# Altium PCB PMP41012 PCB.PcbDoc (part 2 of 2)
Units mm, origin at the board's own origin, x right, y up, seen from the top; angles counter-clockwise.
Board outline 69 x 32 mm, 2 copper layers (Top Layer, Bottom Layer), stack 1.575 mm thick; 63 components, 34 nets, 139 pads, 27 vias.
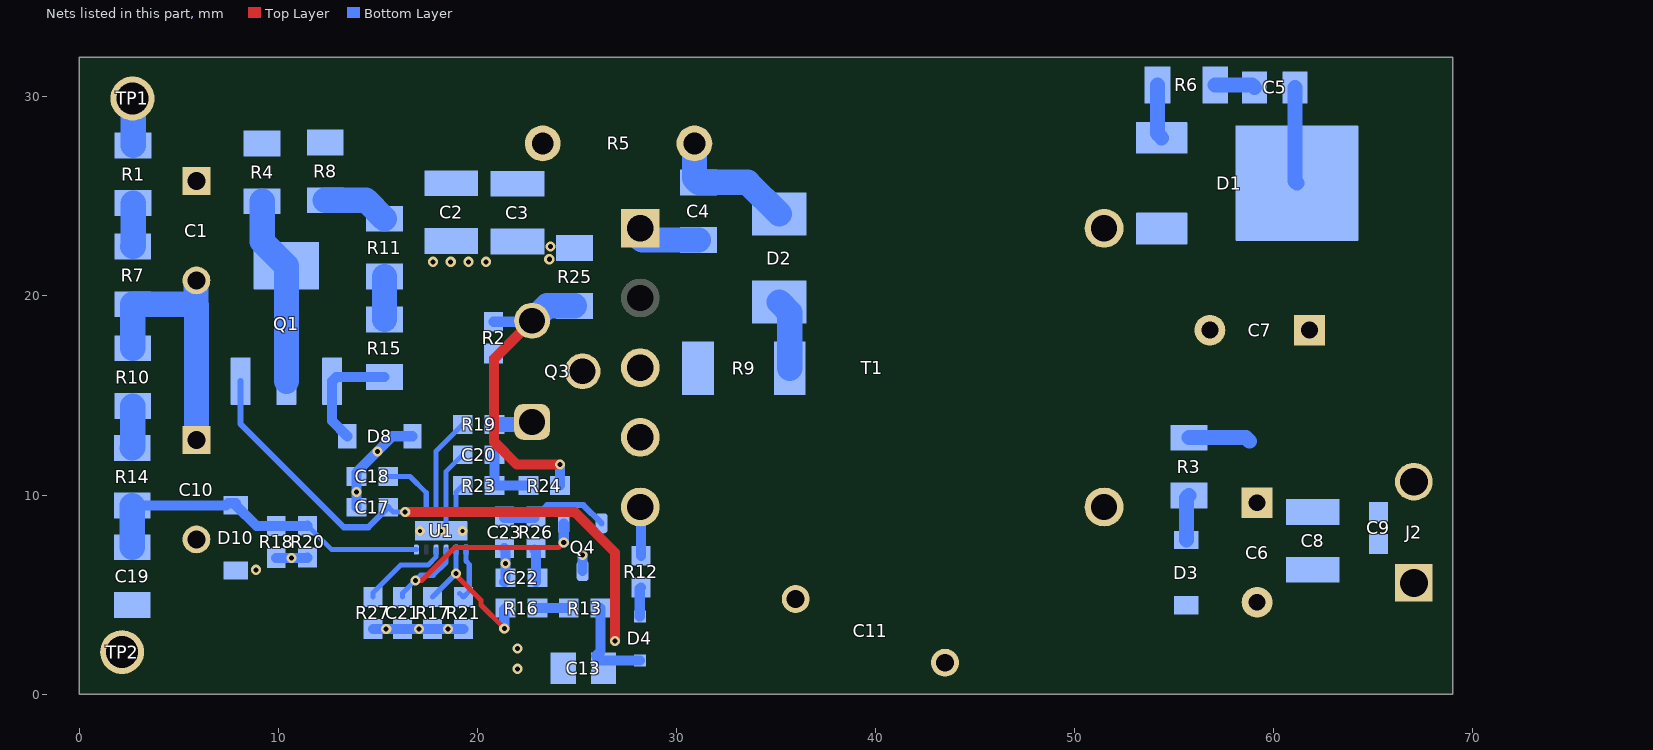
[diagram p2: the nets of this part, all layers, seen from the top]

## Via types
v1: diameter 0.508, hole 0.254, Top Layer to Bottom Layer, 24 vias
v2: diameter 0.5, hole 0.2, Top Layer to Bottom Layer, 3 vias

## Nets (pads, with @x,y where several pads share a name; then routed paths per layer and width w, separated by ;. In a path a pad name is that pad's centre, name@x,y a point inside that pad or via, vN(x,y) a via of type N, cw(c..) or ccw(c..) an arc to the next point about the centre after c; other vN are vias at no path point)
GND: C2.2 C3.2 C10.2 C11.1 C13.2 C17.1 C18.1 C19.2 C20.2 C21.2 C22.2 C23.2 D8.2 D10.2 Q4.3 R17.1 R18.1 R20.1 R21.1 R25.1 R27.1 T1.4 TP2.1 U1.4 U1.13@18.19,8.203 | length 18.1
  Bottom Layer w0.254: v2(18.19,8.203) 18.44,8.453 U1.4@18.44,9.153 18.44,11.189 C20.2@19.275,12.024
  Bottom Layer w0.508: R18.1@9.906,6.845 11.468,6.845 R20.1@11.481,6.858 ; C17.1@13.932,9.385 C18.1@13.932,10.934 13.932,11.138 15.748,12.954 D8.2@16.75,12.954 ; R27.1@14.756,3.276 R17.1@17.756,3.276 R21.1@19.306,3.276 ; C22.2@21.348,5.623 C22.2@21.361,5.636 ; C23.2@21.361,7.328 21.425,7.264 C22.2@21.425,5.842 ; Q4.3@25.298,6.179 v1(25.298,6.985)
  other v1: 22.021,1.27 22.021,2.286 15.428,3.276 17.079,3.276 18.531,3.276 8.89,6.244 21.425,6.553 10.668,6.845 13.932,10.16 14.986,12.192 17.78,21.717 18.669,21.717 19.558,21.717 20.447,21.717 23.622,21.844 23.682,22.479
  other v2: 17.115,8.203 19.265,8.203
NetC1_1: C1.1 C2.1 C3.1 C4.1 R1.2 R4.2 R5.1 R8.2 T1.1 TP1.1 | length 5.4
  Bottom Layer w1.27: TP1.1@2.681,29.921 2.713,29.89 R1.2@2.713,27.562 ; T1.1@28.168,22.925 28.286,22.807 C4.1@31.115,22.807
NetC1_2: C1.2 C10.1 R7.1 R10.2 | length 13.4
  Bottom Layer w1.27: R10.2@2.692,17.376 R7.1@2.692,19.581 5.87,19.581 ; C10.1@5.893,12.772 5.893,19.558 5.87,19.581 ; C1.2@5.893,20.781 5.87,20.758 5.87,19.581
NetC4_2: C4.2 D2.1 R5.2 | length 6.8
  Bottom Layer w1.27: R5.2@30.911,27.665 30.911,25.911 C4.2@31.115,25.707 33.586,25.707 D2.1@35.179,24.115
NetC5_1: C5.1 C6.1 C7.1 C8.1 C9.1 D1.2 J2.2 R3.2 | length 8
  Bottom Layer w0.75: R3.2@55.753,12.88 58.621,12.88 58.801,12.7 ; C5.1@61.087,30.48 61.087,25.764 D1.2@61.185,25.666
NetC5_2: C5.2 R6.2 | length 2
  Bottom Layer w0.75: R6.2@57.076,30.607 58.928,30.607 C5.2@59.055,30.48
NetC13_1: C13.1 C17.2 D4.1 Q1.3 R13.2 U1.1 | length 34.3
  Top Layer w0.508: v1(16.383,9.153) 24.883,9.153 26.924,7.112 v1(26.924,2.667)
  Bottom Layer w0.254: C17.2@15.532,9.385 15.764,9.153 v1(16.383,9.153) U1.1@16.94,9.153
  Bottom Layer w0.305: Q1.3@8.114,15.715 8.114,13.562 13.294,8.382 14.529,8.382 C17.2@15.532,9.385
  Bottom Layer w0.508: R13.2@26.2,4.318 26.2,2.144 25.961,1.905 26.172,1.694 D4.1@28.168,1.694
NetC18_2: C18.2 U1.2 | length 3.2
  Bottom Layer w0.254: C18.2@15.532,10.934 16.625,10.934 17.44,10.119 U1.2@17.44,9.153
NetC19_1: C19.1 D10.1 R14.1 R18.2 R20.2 U1.12 | length 17.4
  Bottom Layer w0.254: R20.2@11.481,8.458 12.685,7.253 U1.12@16.94,7.253
  Bottom Layer w0.508: R14.1@2.667,9.47 7.374,9.47 7.493,9.588 D10.1@7.874,9.588 ; D10.1@7.874,9.489 8.919,8.445 R18.2@9.906,8.445 11.468,8.445 R20.2@11.481,8.458
  Bottom Layer w1.27: C19.1@2.667,7.379 R14.1@2.667,9.47
NetC20_1: C20.1 R23.2 R24.2 | length 3.2
  Bottom Layer w0.508: C20.1@20.875,12.024 R23.2@20.875,10.475 R24.2@22.568,10.475
NetC21_1: C21.1 Q4.1 U1.9 | length 12.9
  Top Layer w0.254: v1(16.891,5.715) 17.222,5.715 18.873,7.366 24.094,7.366 v1(24.348,7.62)
  Bottom Layer w0.254: C21.1@16.256,4.876 16.256,5.08 v1(16.891,5.715) 17.145,5.969 17.796,5.969 18.44,6.613 U1.9@18.44,7.253
  Bottom Layer w0.508: v1(24.348,7.62) Q4.1@24.348,8.579
NetC22_1: C22.1 R26.1 | length 1.7
  Bottom Layer w0.508: R26.1@22.885,7.249 22.948,7.186 C22.1@22.948,5.623
NetC23_1: C23.1 Q4.2 R26.2 U1.6 | length 7.5
  Bottom Layer w0.254: U1.6@19.44,9.153 21.057,9.153 C23.1@21.361,8.849
  Bottom Layer w0.305: R26.2@22.948,8.928 23.51,9.489 25.337,9.489 Q4.2@26.248,8.579
  Bottom Layer w0.508: C23.1@21.361,8.849 R26.2@22.885,8.849
NetD1_1: D1.1 D1.3 R6.1 T1.7 | length 2.7
  Bottom Layer w0.75: R6.1@54.176,30.607 54.176,28.155 D1.3@54.385,27.946
NetD2_2: D2.2 R9.1 | length 3.5
  Bottom Layer w1.27: D2.2@35.179,19.695 35.701,19.173 R9.1@35.701,16.367
NetD3_1: D3.1 R3.1 | length 2.3
  Bottom Layer w0.75: D3.1@55.626,7.733 55.626,9.853 R3.1@55.753,9.98
NetD4_2: D4.2 R12.1 | length 1.5
  Bottom Layer w0.508: D4.2@28.168,3.894 28.168,5.296 R12.1@28.219,5.347
NetD8_1: D8.1 Q1.1 R15.1 | length 5.8
  Bottom Layer w0.508: D8.1@13.476,12.954 12.714,13.715 Q1.1@12.714,15.715 12.92,15.921 R15.1@15.342,15.921
NetQ1_2: Q1.2 Q1.4 R4.1 | length 9.6
  Bottom Layer w1.27: R4.1@9.194,24.76 9.194,22.735 Q1.4@10.414,21.515 Q1.2@10.414,15.715
NetQ3_1: Q3.1 R2.2 R19.1 | length 5.2
  Bottom Layer w0.508: R2.2@20.853,16.812 20.853,13.57 R19.1@20.875,13.548
  Bottom Layer w0.762: R19.1@20.875,13.548 22.631,13.548 Q3.1@22.758,13.675
NetQ3_2: Q3.2 R9.2 T1.3
NetQ3_3: Q3.3 R2.1 R24.1 R25.2 | length 16.1
  Top Layer w0.508: Q3.3@22.758,18.755 20.853,16.85 20.853,12.675 22.002,11.526 v1(24.168,11.526)
  Bottom Layer w0.508: R2.1@20.828,18.707 22.71,18.707 Q3.3@22.758,18.755 ; R24.1@24.168,10.475 v1(24.168,11.526)
  Bottom Layer w1.27: Q3.3@22.758,18.755 23.508,19.505 R25.2@24.892,19.505
NetR1_1: R1.1 R7.2 | length 2.2
  Bottom Layer w1.27: R7.2@2.692,22.481 2.713,22.501 R1.1@2.713,24.662
NetR8_1: R8.1 R11.2 | length 3.4
  Bottom Layer w1.27: R8.1@12.369,24.811 14.409,24.811 R11.2@15.342,23.878
NetR10_1: R10.1 R14.2 | length 2.1
  Bottom Layer w1.27: R14.2@2.667,12.37 2.692,12.395 R10.1@2.692,14.476
NetR11_1: R11.1 R15.2 | length 2.2
  Bottom Layer w1.27: R15.2@15.342,18.821 R11.1@15.342,20.978
NetR12_2: R12.2 T1.5 | length 2
  Bottom Layer w0.508: T1.5@28.168,8.925 28.219,8.874 R12.2@28.219,6.947
NetR13_1: R13.1 R16.2 | length 1.6
  Bottom Layer w0.508: R16.2@23.025,4.318 R13.1@24.6,4.318
NetR19_2: R19.2 U1.3 | length 4.9
  Bottom Layer w0.254: U1.3@17.94,9.153 17.94,12.213 R19.2@19.275,13.548
NetR21_2: R21.2 U1.7 | length 2.8
  Bottom Layer w0.254: R21.2@19.12,5.062 R21.2@19.306,4.876 19.6,5.17 19.6,6.52 19.44,6.681 U1.7@19.44,7.253
NetR23_1: R23.1 U1.5 | length 1.5
  Bottom Layer w0.254: U1.5@18.94,9.153 18.94,10.14 R23.1@19.275,10.475
NetR27_2: R27.2 U1.10 | length 4.5
  Bottom Layer w0.254: R27.2@14.756,4.876 14.756,5.082 16.151,6.477 17.524,6.477 17.94,6.893 U1.10@17.94,7.253
SGND: C6.2 C7.2 C8.2 C9.2 C11.2 D3.2 J2.1 T1.6
VFB: R16.1 R17.2 U1.8 | length 7.6
  Top Layer w0.254: v1@18.94,5.969 20.193,4.716 20.193,4.47 v1(21.361,3.302)
  Bottom Layer w0.254: R17.2@17.756,4.876 v1(18.94,6.06) U1.8@18.94,7.253
  Bottom Layer w0.508: v1(21.361,3.302) 21.361,4.254 R16.1@21.425,4.318
pads on no net: T1.2 U1.11 U1.13@17.505,8.203 U1.13@18.875,8.203

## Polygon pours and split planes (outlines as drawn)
GND on Bottom Layer "BOTTOM_LAYER_GND_P000" (solid, remove dead copper, pour order 0): 17.462,9.652 17.16,9.652 16.256,8.747 16.256,7.649 16.151,7.544 16.595,7.1 19.285,7.1 19.979,6.406 19.979,4.178 19.901,4.1 14.41,4.1 14.351,4.159 14.351,1.778 15.748,0.381 25.336,0.381 25.336,5.005 20.679,9.663
GND on Bottom Layer "BOTTOM_LAYER_GND_P024" (solid, remove dead copper, pour order 24): 3.302,0.889 7.874,5.461 11.155,5.461 12.065,6.371 12.065,7.252 11.824,7.493 8.128,7.493 7.042,8.579 5.404,8.579 4.572,7.747 4.572,5.969 3.81,5.207 1.339,5.207 0.889,4.757 0.889,1.143 1.143,0.889
SGND on Bottom Layer "BOTTOM_LAYER_SGND_P020" (solid, remove dead copper, pour order 20): 56.642,21.209 57.531,20.32 57.531,17.739 54.102,14.31 54.102,7.175 54.928,6.35 59.093,6.35 60.871,8.128 67.335,8.128 68.7,6.763 68.7,2.66 66.802,0.762 42.926,0.762 42.291,1.397 42.291,2.286 46.228,6.223 46.228,18.415 49.022,21.209
NetD1_1 on Bottom Layer "BOTTOM_LAYER_NETD1_1_P014" (solid, remove dead copper, pour order 14): 51.054,21.59 55.118,21.59 55.753,22.225 55.753,28.702 55.499,28.956 53.213,28.956 50.419,26.162 50.419,22.225
NetC5_1 on Bottom Layer "BOTTOM_LAYER_NETC5_1_P012" (solid, remove dead copper, pour order 12): 62.738,12.425 61.087,10.774 61.087,10.298 61.352,10.033 64.389,10.033 66.548,12.192 67.691,12.192 68.326,11.557 68.326,9.563 67.145,8.382 58.674,8.382 57.658,9.398 57.658,16.637 58.928,17.907 60.706,17.907 60.833,18.034 60.833,18.383 60.674,18.542 59.055,18.542 57.912,19.685 57.912,21.59 57.912,28.448 58.293,28.829 64.135,28.829 64.643,28.321 64.643,19.05 62.738,17.145
GND on Bottom Layer "BOTTOM_LAYER_GND_P010" (solid, remove dead copper, pour order 10): 25.527,21.336 25.908,21.717 25.908,23.241 25.527,23.622 17.399,23.622 17.272,23.495 17.272,21.504 17.44,21.336
NetC1_1 on Bottom Layer "BOTTOM_LAYER_NETC1_1_P006" (solid, remove dead copper, pour order 6): 26.035,24.892 27.178,23.749 27.178,21.971 27.305,21.844 29.083,21.844 29.21,21.971 29.21,23.876 24.13,28.956 5.969,28.956 3.683,31.242 1.651,31.242 1.27,30.861 1.27,27.432 1.778,26.924 4.572,26.924 5.08,26.416 5.08,25.146 5.207,25.019 6.604,25.019 6.731,25.146 6.731,26.67 7.112,27.051 16.383,27.051 17.272,26.162 17.272,25.019 17.399,24.892
NetQ3_2 on Bottom Layer "BOTTOM_LAYER_NETQ3_2_P004" (solid, remove dead copper, pour order 4): 24.859,15.4 29.8,15.4 30.341,14.859 31.75,14.859 32.004,15.113 32.004,17.78 31.877,17.907 30.353,17.907 29.822,17.376 25.076,17.376 24.348,16.648 24.348,15.911
NetC13_1 on Bottom Layer "BOTTOM_LAYER_NETC13_1_P002" (solid, remove dead copper, pour order 2): 25.654,0.682 25.955,0.381 27.559,0.381 28.575,1.397 28.575,2.032 26.797,3.81 26.797,4.826 26.67,4.953 25.781,4.953 25.654,4.826
SGND on Top Layer "TOP_LAYER_SGND_P028" (solid, remove dead copper, pour order 28): 42.799,1.143 43.18,0.762 68.326,0.762 68.7,1.136 68.7,30.995 68.072,31.623 54.61,31.623 48.387,25.4 48.387,7.493 42.799,1.905
GND on Top Layer "TOP_LAYER_GND_P018" (solid, remove dead copper, pour order 18): 34.544,4.064 36.322,4.064 36.703,4.445 36.703,8.763 31.481,13.985 27.447,13.985 24.511,11.049 21.24,11.049 19.843,12.446 19.843,20.605 20.278,21.04 23.58,21.04 24.348,21.808 24.348,22.642 23.622,23.368 10.414,23.368 8.001,20.955 8.001,10.414 6.76,9.173 4.376,9.173 0.889,5.686 0.889,1.397 1.397,0.889 3.302,0.889 6.35,3.937 10.287,3.937 11.638,5.288 11.638,18.369 14.05,20.781 15.414,20.781 15.748,20.447 15.748,16.525 13.208,13.985 13.208,1.905 14.224,0.889 24.892,0.889 25.781,1.778 25.781,8.89 27.94,11.049 30.607,11.049 33.782,7.874 33.782,4.826

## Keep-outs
Keep-Out Layer:
  text ".Layer_Name" at 14.656,-21.806 h1.52

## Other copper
Top Layer:
  text ".Layer_Name" at 14.656,-21.806 h1.52
Bottom Layer:
  text ".Layer_Name" at 14.656,-21.806 h1.52

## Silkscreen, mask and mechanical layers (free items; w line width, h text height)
Top Overlay:
  text "DC+" at 4.826,30.353 h1.85
  text "+" at 67.4,14.6 h1.85
  text "DC-" at 4.572,1.524 h1.85
  text "-" at 67.6,0.9 h1.85
  text "PMP41012" at 45.9,0.8 h1.85
  text ".Layer_Name" at 14.656,-21.806 h1.52
Bottom Overlay:
  lines w0.152: 29.21,8.128 26.924,8.128 26.924,9.652 20.262,9.652 20.262,0.45 20.585,0.127 28.887,0.127 29.21,0.45 29.21,1.778 ; 29.21,1.778 29.21,9.144 35.052,9.144 35.052,8.382 35.052,1.778 29.21,1.778
  text ".Layer_Name" at 14.656,-21.806 h1.52
Top Paste:
  text ".Layer_Name" at 14.656,-21.806 h1.52
Bottom Paste:
  text ".Layer_Name" at 14.656,-21.806 h1.52
Top Solder:
  text ".Layer_Name" at 14.656,-21.806 h1.52
  text ".Layer_Name" at 14.656,-21.806 h1.52
Bottom Solder:
  text ".Layer_Name" at 14.656,-21.806 h1.52
Drill Guide:
  text ".Layer_Name" at 14.656,-21.806 h1.52
M1 Board Outline:
  the board outline again, w0.254
  text ".Layer_Name" at 14.656,-21.806 h1.52
M2 Board Dimensions:
  rectangle: 0,-6.985 3.175,-3.81
  rectangle: 3.175,-10.16 12.7,-6.985
  lines w0.178: 0,-6.985 25.4,-6.985 ; 3.175,-10.16 3.175,-3.81 ; 6.35,-10.16 6.35,-3.81 ; 12.7,-10.16 12.7,-3.81 ; 19.05,-10.16 19.05,-3.81 ; 0,-10.16 25.4,-10.16 25.4,-3.81 0,-3.81 0,-10.16
  text ".Layer_Name" at 14.656,-21.806 h1.52
M3 3D STEP Top:
  text ".Layer_Name" at 14.656,-21.806 h1.52
M4 3D STEP Bottom:
  text ".Layer_Name" at 14.656,-21.806 h1.52
M5 Assembly Top:
  lines w0.254: -7.417,-23.626 160.223,-23.626 ; -7.417,-18.462 160.274,-18.462 ; -7.417,-13.297 -7.417,-28.791 94.31,-28.791 160.274,-28.791 160.274,-13.297 -7.404,-13.297 -7.404,-28.791 32.614,-28.791 ; 55.194,-28.791 55.194,-13.297 ; 87.376,-18.462 87.376,-13.297 ; 108.712,-18.462 108.712,-13.297 ; 124.511,-28.956 124.511,-23.804
  text "COMPONENTS MARKED 'DNP' SHOULD NOT BE POPULATED." at 29.299,-8.09 h1.52
  text "ASSEMBLY VARIANT:" at 29.286,-11.024 h1.52
  text ".VariantName" at 55.601,-11.024 h1.52
  text "PCB VIEWED FROM TOP SIDE" at -5.804,-16.654 h1.52
  text "BOARD #:" at 57.099,-16.654 h1.52
  text ".PRJ_Number" at 70.955,-16.654 h1.52
  text "REV:" at 92.405,-16.654 h1.52
  text ".PCB_Rev" at 99.809,-16.654 h1.52
  text "SVN REV:" at 113.69,-16.654 h1.52
  text ".VersionControl_RevNumber" at 126.543,-16.654 h1.52
  text "TID #:" at 57.099,-21.819 h1.52
  text ".TID" at 70.955,-21.819 h1.52
  text "PLOT NAME =" at -5.804,-27.034 h1.52
  text ".plot_File_Name" at 14.656,-27.034 h1.52
  text "GENERATED    :" at 57.15,-27.034 h1.52
  text ".Print_Date" at 79.235,-27.034 h1.52
  text ".Print_Time" at 97.752,-27.034 h1.52
  text "TEXAS INSTRUMENTS" at 129.87,-27.034 h1.52
M6 Assembly Bottom:
  lines w0.254: -7.429,-18.474 160.261,-18.474 ; -7.379,-23.639 160.261,-23.639 ; 28.334,-28.969 28.334,-23.817 ; 44.133,-18.474 44.133,-13.31 ; 65.468,-18.474 65.468,-13.31 ; 97.65,-28.804 97.65,-13.31 ; 120.231,-28.804 160.249,-28.804 160.249,-13.31 -7.429,-13.31 -7.429,-28.804 58.534,-28.804 160.261,-28.804 160.261,-13.31
  text "COMPONENTS MARKED 'DNP' SHOULD NOT BE POPULATED." at 154.991,-8.077 h1.52
  text ".VariantName" at 128.473,-11.024 h1.52
  text "ASSEMBLY VARIANT:" at 154.864,-11.024 h1.52
  text ".VersionControl_RevNumber" at 26.302,-16.667 h1.52
  text "SVN REV:" at 39.154,-16.667 h1.52
  text ".PCB_Rev" at 53.035,-16.667 h1.52
  text "REV:" at 60.439,-16.667 h1.52
  text ".PRJ_Number" at 81.89,-16.667 h1.52
  text "BOARD #:" at 95.745,-16.667 h1.52
  text "PCB VIEWED FROM BOTTOM SIDE" at 158.648,-16.667 h1.52
  text ".TID" at 81.89,-21.831 h1.52
  text "TID #:" at 95.745,-21.831 h1.52
  text "TEXAS INSTRUMENTS" at 22.974,-27.047 h1.52
  text ".Print_Time" at 55.093,-27.047 h1.52
  text ".Print_Date" at 73.609,-27.047 h1.52
  text "GENERATED    :" at 95.694,-27.047 h1.52
  text ".plot_File_Name" at 138.189,-27.047 h1.52
  text "PLOT NAME =" at 158.648,-27.047 h1.52
M9 Title Sheet:
  drawing of 57 lines, arcs and shapes, not listed
  text "1" at 18.792,204.127 h1.78
  text "2" at 82.182,204.127 h1.78
  text "3" at 145.411,204.127 h1.78
  text "4" at 209.08,204.127 h1.78
  text "5" at 272.555,204.127 h1.78
  text "6" at 336.182,204.127 h1.78
  text "A" at -10.579,175.095 h1.78
  text "A" at 365.341,175.095 h1.78
  text "B" at -10.579,114.643 h1.78
  text "B" at 365.341,114.643 h1.78
  text "C" at -10.579,54.318 h1.78
  text "C" at 365.341,54.318 h1.78
  text "PROJECT TITLE:" at 288.125,7.048 h1.14
  text ".PRJ_Title" at 289.395,3.662 h1.78
  text "DESIGNED FOR:" at 288.125,-0.597 h1.14
  text ".PRJ_Customer" at 289.395,-4.153 h1.78
  text "D" at -10.579,-5.88 h1.78
  text "D" at 365.341,-5.88 h1.78
  text "FILE NAME:" at 288.125,-8.217 h1.14
  text ".PCB_File_Name_No_Path" at 289.395,-11.265 h1.78
  text "Texas Instruments (TI) and/or its licensors do not warrant the accuracy or completeness of this specification" at 161.9,-15.376 h1.14
  text "ENGINEER:" at 288.125,-15.583 h1.14
  text "LAYOUT BY:" at 326.352,-15.583 h1.14
  text "or any information contained therein. TI and/or its licensors do not warrant that this design will meet" at 160.757,-18.237 h1.14
  text ".PRJ_Engineer" at 289.395,-19.52 h1.78
  text ".PCB_Layout" at 327.635,-19.52 h1.78
  text "the specifications, will be suitable for your application or fit for any particular purpose, or will operate in" at 160.757,-21.099 h1.14
  text ".Layer_Name" at 14.656,-21.806 h1.52
  text "ALTIUM DESIGNER VERSION:" at 326.352,-23.457 h1.14
  text "an implementation. TI and/or its licensors do not warrant that the design is production worthy. You should" at 160.757,-23.961 h1.14
  text "completely validate and test your design implementation to confirm the system functionality for your application." at 161.9,-26.822 h1.14
  text ".print_Scale" at 289.395,-26.843 h1.78
  text ".Application_BuildNumber" at 327.635,-26.843 h1.78
  text "1" at 18.792,-32.093 h1.78
  text "2" at 82.182,-32.093 h1.78
  text "3" at 145.411,-32.093 h1.78
  text "4" at 209.08,-32.093 h1.78
  text "5" at 272.555,-32.093 h1.78
  text "6" at 336.182,-32.093 h1.78
M10 Fab Notes:
  drawing of 189 lines, arcs and shapes, not listed
  text "DESIGN INFORMATION" at 314.503,161.447 h1.52
  text "MIN. TRACK WIDTH:" at 298.131,158.091 h1.52
  text "8" at 325.976,158.091 h1.52
  text "MIL" at 329.907,158.091 h1.52
  text "MIN. CLEARANCE:" at 298.131,154.938 h1.52
  text "0.2" at 324.452,154.938 h1.52
  text "mm" at 329.907,154.938 h1.52
  text "MIN. VIA PAD SIZE:" at 298.131,151.785 h1.52
  text "24" at 325.214,151.785 h1.52
  text "MIL" at 329.907,151.785 h1.52
  text "0.05mm (2MIL)" at 315.784,148.486 h1.52
  text "MINIMUM ANNULAR RING" at 289.769,148.277 h1.52
  text "EXTERNAL" at 333.768,148.277 h1.52
  text "PER" at 294.849,145.48 h1.52
  text "IPC-D-275 CLASS 2 LEVEL C" at 300.437,145.48 h1.52
  text "MIL, HOLES" at 338.238,142.928 h1.52
  text "+/-" at 328.27,142.709 h1.52
  text "+/-" at 349.961,142.709 h1.52
  text "REGISTRATION TOLERANCES:" at 289.769,142.682 h1.52
  text "METAL" at 320.243,142.682 h1.52
  text "5" at 334.879,142.683 h1.52
  text "3" at 356.037,142.683 h1.52
  text "MIL" at 358.99,142.682 h1.52
  text "HOLE SIZE TOLERANCE (UNLESS OTHERWISE SPECIFIED):" at 289.769,140.185 h1.52
  text "+/-" at 349.961,140.112 h1.52
  text "3" at 356.037,140.085 h1.52
  text "MIL" at 358.99,140.085 h1.52
  text "MATERIAL:" at 287.87,136.589 h1.52
  text "FR-4 High Tg" at 312.926,133.324 h1.52
  text "X" at 309.257,133.122 h1.52
  text "FR-408" at 298.563,133.007 h1.52
  text "OTHER" at 336.358,133.007 h1.52
  text "62 MIL (1.6mm) +/-10%" at 306.694,129.374 h1.52
  text "X" at 303.643,129.312 h1.52
  text "THICKNESS:" at 289.769,129.165 h1.52
  text "OTHER" at 339.33,129.165 h1.52
  text "TOLERANCE:" at 289.769,125.652 h1.52
  text "X" at 311.314,125.652 h1.52
  text "ANSI IPC-6012 TYPE 3 CLASS 2" at 315.836,125.652 h1.52
  text "OTHER +/-" at 315.835,121.989 h1.52
  text "BOW & TWIST:" at 289.769,118.302 h1.52
  text "X" at 311.314,118.302 h1.52
  text "ANSI IPC-6012 TYPE 3 CLASS 2" at 315.836,118.302 h1.52
  text "OTHER +/-" at 315.835,114.576 h1.52
  text "DRILLING:" at 287.87,111.258 h1.52
  text "NC_DRILL FILES" at 332.599,108.586 h1.52
  text "REFERENCE:" at 289.769,108.486 h1.52
  text "X" at 306.463,108.484 h1.52
  text "AS SHOWN" at 310.984,108.486 h1.52
  text "X" at 329.348,108.486 h1.52
  text "OTHER" at 340.168,104.873 h1.52
  text "PTH COPPER THICKNESS:" at 289.761,104.783 h1.52
  text "X" at 318.697,104.783 h1.52
  text "20-30 um" at 321.948,104.783 h1.52
  text "BOARD FINISH:" at 287.87,101.034 h1.52
  text "SILKSCREEN:" at 291.812,98.237 h1.52
  text "X" at 316.14,98.237 h1.52
  text "TOP" at 319.112,98.237 h1.52
  text "X" at 329.094,98.237 h1.52
  text "BOTTOM" at 332.091,98.237 h1.52
  text "SILKSCREEN COLOR:" at 291.812,94.295 h1.52
  text "X" at 316.115,94.295 h1.52
  text "WHITE" at 319.112,94.295 h1.52
  text "OTHER" at 332.091,94.295 h1.52
  text "X" at 319.442,90.652 h1.52
  text "GREEN" at 322.439,90.652 h1.52
  text "OTHER" at 338.136,90.652 h1.52
  text "SOLDER RESIST COLOR:" at 291.812,90.477 h1.52
  text "X" at 319.442,86.734 h1.52
  text "MATTE" at 322.439,86.734 h1.52
  text "SEMI-GLOSS" at 338.125,86.717 h1.52
  text "IMMERSION GOLD (ENIG)" at 314.819,82.345 h1.52
  text "ENEPIG" at 348.793,82.162 h1.52
  text "SURFACE FINISH:" at 287.87,82.136 h1.52
  text "X" at 310.298,82.136 h1.52
  text "IMM. TIN/SILVER OR EQUIV" at 296.24,78.649 h1.52
  text "OTHER" at 332.599,78.549 h1.52
  text "ARRAY/PANEL:" at 287.87,74.602 h1.52
  text "CUT AND TRIM PER M1 BOARD OUTLINE" at 314.819,74.393 h1.52
  text "N.C. ROUTE" at 314.819,70.94 h1.52
  text "X" at 332.295,70.94 h1.52
  text "V. SCORE" at 336.816,70.94 h1.52
  text "CERTIFICATION:" at 287.87,67.66 h1.52
  text "MATERIALS AND WORKMANSHIP FOR ALL PCBS" at 306.285,67.66 h1.52
  text "TO MEET OR EXCEED THE REQUIREMENTS OF:" at 306.285,65.271 h1.52
  text "X" at 297.078,62.003 h1.52
  text "ANSI IPC-A-600F CLASS ->" at 300.329,62.003 h1.52
  text "X" at 342.188,62.003 h1.52
  text "2" at 344.982,62.003 h1.52
  text "1" at 336.981,61.965 h1.52
  text "3" at 353.973,61.965 h1.52
  text "X" at 317.702,58.252 h1.52
  text "RoHS" at 320.953,58.252 h1.52
  text "OTHER" at 337.321,58.252 h1.52
  text "PER ORDER" at 347.407,58.252 h1.52
  text "ALL BOARDS MUST MEET OR EXCEED UL94-V0 REQUIREMENTS." at 288.569,54.345 h1.52
  text "PCB MUST BEAR THE UL94V-0 UL REGISTERED MATERIAL ID NUMBER" at 288.569,51.397 h1.52
  text "ADDITIONAL REQUIREMENTS:" at 287.87,47.094 h1.52
  text "MICROSECTION:" at 289.769,44.373 h1.52
  text "YES" at 312.775,44.373 h1.52
  text "REQUIRED" at 334.657,40.707 h1.52
  text "BARE BOARD ELEC. TEST:" at 289.769,40.634 h1.52
  text "NONE" at 322.935,40.634 h1.52
  text "X" at 331.66,40.634 h1.52
  text "PER ORDER" at 349.693,40.634 h1.52
  text "XX MIL VIAS REQUIRE NON-CONDUCTIVE FILL AND PLANARIZE" at 294.04,35.428 h1.5
  text "XX MIL VIAS REQUIRE CONDUCTIVE FILL AND PLANARIZE" at 294.243,32.787 h1.52
  text "OUTER XX MIL TRACES REQUIRE 50 OHM SINGLE-ENDED IMPEDANCE" at 294.218,28.637 h1.47
  text "LAYER 2 & 3 (INNER LAYERS) XX MIL WIDE, XX MIL SPACE / TRACES REQUIRE 100 OHM DIFFERENTIAL IMPEDANCE" at 294.015,22.65 h1.52
  text ".Layer_Name" at 14.656,-21.806 h1.52
M11 Gerber Information:
  lines w0.254: -7.417,-23.626 160.223,-23.626 ; -7.417,-18.462 160.274,-18.462 ; -7.417,-13.297 -7.417,-28.791 94.31,-28.791 160.274,-28.791 160.274,-13.297 -7.404,-13.297 -7.404,-28.791 32.614,-28.791 ; 55.194,-28.791 55.194,-13.297 ; 87.376,-18.462 87.376,-13.297 ; 108.712,-18.462 108.712,-13.297 ; 124.511,-28.956 124.511,-23.804
  text "ALL ARTWORK VIEWED FROM TOP SIDE" at -5.804,-16.654 h1.52
  text "BOARD #:" at 57.099,-16.654 h1.52
  text ".PRJ_Number" at 70.955,-16.654 h1.52
  text "REV:" at 92.405,-16.654 h1.52
  text ".PCB_Rev" at 99.809,-16.654 h1.52
  text "SVN REV:" at 113.69,-16.654 h1.52
  text ".VersionControl_RevNumber" at 126.543,-16.654 h1.52
  text "LAYER NAME =" at -5.804,-21.806 h1.52
  text "TID #:" at 57.099,-21.819 h1.52
  text ".TID" at 70.955,-21.819 h1.52
  text "PLOT NAME =" at -5.804,-27.034 h1.52
  text ".plot_File_Name" at 14.656,-27.034 h1.52
  text "GENERATED    :" at 57.15,-27.034 h1.52
  text ".Print_Date" at 79.235,-27.034 h1.52
  text ".Print_Time" at 97.752,-27.034 h1.52
  text "TEXAS INSTRUMENTS" at 129.87,-27.034 h1.52
M12 Stackup:
  drawing of 191 lines, arcs and shapes, not listed
  text "Layer" at 249.215,197.166 h1.52
  text "Name" at 259.626,197.166 h1.52
  text "Material" at 283.242,197.166 h1.52
  text "Thickness" at 305.08,197.166 h1.52
  text "Constant" at 321.586,197.166 h1.52
  text "Board Layer Stack" at 336.06,197.166 h1.52
  text "1" at 249.215,194.118 h1.52
  text "Top Overlay" at 259.626,194.118 h1.52
  text "2" at 249.215,191.07 h1.52
  text "Top Solder" at 259.626,191.07 h1.52
  text "Solder Resist" at 283.242,191.07 h1.52
  text "0.40mil" at 305.08,191.07 h1.52
  text "3.5" at 321.586,191.07 h1.52
  text "3" at 249.215,188.022 h1.52
  text "Top Layer" at 259.626,188.022 h1.52
  text "Copper" at 283.242,188.022 h1.52
  text "1.40mil" at 305.08,188.022 h1.52
  text "4" at 249.215,184.974 h1.52
  text "Dielectric1" at 259.626,184.974 h1.52
  text "FR-4" at 283.242,184.974 h1.52
  text "59.20mil" at 305.08,184.974 h1.52
  text "4.8" at 321.586,184.974 h1.52
  text "5" at 249.215,181.926 h1.52
  text "Bottom Layer" at 259.626,181.926 h1.52
  text "Copper" at 283.242,181.926 h1.52
  text "1.40mil" at 305.08,181.926 h1.52
  text "6" at 249.215,178.878 h1.52
  text "Bottom Solder" at 259.626,178.878 h1.52
  text "Solder Resist" at 283.242,178.878 h1.52
  text "0.40mil" at 305.08,178.878 h1.52
  text "3.5" at 321.586,178.878 h1.52
  text "7" at 249.215,175.83 h1.52
  text "Bottom Overlay" at 259.626,175.83 h1.52
  text ".Layer_Name" at 14.656,-21.806 h1.52
M13 Component Bodies Top:
  text ".Layer_Name" at 14.656,-21.806 h1.52
M14 Component Bodies Bottom:
  text ".Layer_Name" at 14.656,-21.806 h1.52
M15 Courtyards Top:
  text ".Layer_Name" at 14.656,-21.806 h1.52
M16 Courtyards Bottom:
  text ".Layer_Name" at 14.656,-21.806 h1.52
Drill Drawing:
  circle w0.254: c136.238,71.704 r0.421
  circle w0.254: c136.238,71.704 r0.702
  circle w0.254: c136.238,59.073 r0.702
  lines w0.254: 135.537,61.88 135.888,61.88 136.238,61.529 136.589,61.88 136.94,61.88 136.589,62.231 136.94,62.582 136.589,62.582 136.238,62.933 135.888,62.582 135.537,62.582 135.888,62.231 135.537,61.88 ; 135.537,64.687 136.94,64.687 136.94,66.091 135.537,66.091 135.537,64.687 ; 135.537,68.547 136.238,67.845 136.94,68.547 136.238,69.248 135.537,68.547 ; 135.537,74.16 136.94,74.16 136.94,75.564 135.537,75.564 135.537,74.16 ; 135.537,78.721 136.94,78.721 136.238,77.318 135.537,78.721 ; 135.537,80.476 136.238,80.827 136.94,80.476 136.589,81.177 136.94,81.879 136.238,81.528 135.537,81.879 135.888,81.177 135.537,80.476 ; 135.537,83.984 135.888,83.984 135.888,83.633 136.589,83.633 136.589,83.984 136.94,83.984 136.94,84.686 136.589,84.686 136.589,85.037 135.888,85.037 135.888,84.686 135.537,84.686 135.537,83.984 ; 135.817,64.968 136.659,64.968 136.659,65.81 135.817,65.81 135.817,64.968
  lines w0.305: 134.264,57.424 216.344,57.424 ; 134.264,85.844 216.344,85.844 ; 142.846,54.267 142.846,89.002 ; 151.279,54.267 151.279,89.002 ; 167.448,54.267 167.448,89.002 ; 174.03,54.267 174.03,89.002 ; 183.559,54.267 183.559,89.002 ; 201.957,54.267 201.957,89.002 ; 134.264,54.267 216.344,54.267 216.344,89.002 134.264,89.002 134.264,54.267
  text "Symbol" at 136.159,86.791 h1.83
  text "Quantity" at 143.793,86.791 h1.83
  text "Finished Hole Size" at 152.226,86.791 h1.83
  text "Plated" at 168.395,86.791 h1.83
  text "Hole Type" at 174.977,86.791 h1.83
  text "Drill Layer Pair" at 184.506,86.791 h1.83
  text "Hole Tolerance" at 202.904,86.791 h1.83
  text "3" at 143.793,83.633 h1.52
  text "7.87mil (0.200mm)" at 152.226,83.633 h1.52
  text "PTH" at 168.395,83.633 h1.52
  text "Round" at 174.977,83.633 h1.52
  text "Top Layer - Bottom Layer" at 184.506,83.633 h1.52
  text "24" at 143.793,80.476 h1.52
  text "10.00mil (0.254mm)" at 152.226,80.476 h1.52
  text "PTH" at 168.395,80.476 h1.52
  text "Round" at 174.977,80.476 h1.52
  text "Top Layer - Bottom Layer" at 184.506,80.476 h1.52
  text "4" at 143.793,77.318 h1.52
  text "33.47mil (0.850mm)" at 152.226,77.318 h1.52
  text "PTH" at 168.395,77.318 h1.52
  text "Round" at 174.977,77.318 h1.52
  text "Top Layer - Bottom Layer" at 184.506,77.318 h1.52
  text "6" at 143.793,74.16 h1.52
  text "35.43mil (0.900mm)" at 152.226,74.16 h1.52
  text "PTH" at 168.395,74.16 h1.52
  text "Round" at 174.977,74.16 h1.52
  text "Top Layer - Bottom Layer" at 184.506,74.16 h1.52
  text "2" at 143.793,71.003 h1.52
  text "43.31mil (1.100mm)" at 152.226,71.003 h1.52
  text "PTH" at 168.395,71.003 h1.52
  text "Round" at 174.977,71.003 h1.52
  text "Top Layer - Bottom Layer" at 184.506,71.003 h1.52
  text "3" at 143.793,67.845 h1.52
  text "51.18mil (1.300mm)" at 152.226,67.845 h1.52
  text "PTH" at 168.395,67.845 h1.52
  text "Round" at 174.977,67.845 h1.52
  text "Top Layer - Bottom Layer" at 184.506,67.845 h1.52
  text "7" at 143.793,64.687 h1.52
  text "51.97mil (1.320mm)" at 152.226,64.687 h1.52
  text "PTH" at 168.395,64.687 h1.52
  text "Round" at 174.977,64.687 h1.52
  text "Top Layer - Bottom Layer" at 184.506,64.687 h1.52
  text "2" at 143.793,61.529 h1.52
  text "55.12mil (1.400mm)" at 152.226,61.529 h1.52
  text "PTH" at 168.395,61.529 h1.52
  text "Round" at 174.977,61.529 h1.52
  text "Top Layer - Bottom Layer" at 184.506,61.529 h1.52
  text "2" at 143.793,58.372 h1.52
  text "63.00mil (1.600mm)" at 152.226,58.372 h1.52
  text "PTH" at 168.395,58.372 h1.52
  text "Round" at 174.977,58.372 h1.52
  text "Top Layer - Bottom Layer" at 184.506,58.372 h1.52
  text "53 Total" at 143.793,55.214 h1.52
  text ".Layer_Name" at 14.656,-21.806 h1.52
M17 Embedded Cavity:
  text ".Layer_Name" at 14.656,-21.806 h1.52
M18 Embedded Assembly:
  text ".Layer_Name" at 14.656,-21.806 h1.52
M19 Embedded Keepout:
  text ".Layer_Name" at 14.656,-21.806 h1.52

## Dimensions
0,0 to 0,32 on M2 Board Dimensions
0,-10.16 to 25.4,-10.16 on M2 Board Dimensions
0,0 to 69,0 on M2 Board Dimensions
